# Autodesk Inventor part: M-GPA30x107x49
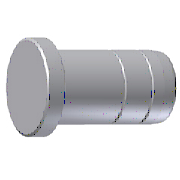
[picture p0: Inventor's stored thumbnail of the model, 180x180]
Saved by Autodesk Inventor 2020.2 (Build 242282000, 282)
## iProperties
Created: 2019-01
Part Number: M-GPA30x107x49
Material: SUJ 2
Description: KOŁEK PROWADZĄCY
Document SubType Name: Modeling
Designer: F.Stasiak
Standard Revision: 1
Manufacturer: FUTABA
Language: pl-PL
Size Designation: 30x107x49
Categories: <MemberInstance><Categories><Category DisplayName="Forma wtryskowa" InternalName="349578f2-f4d4-4954-8c09-8e99297a61c0" Mnemonic="MOLD"><Category DisplayName="K
Mass: 12.6115 g
Surface Area: 36.5267 cm^2
Volume: 12.6115 cm^3
Density: 7.85 g/cm^3
Appearance: Domyślna
Catalog Web Link: www.expertbooks.pl
Manager: www.cadconsulting.pl
Company: Fabian Stasiak CAD Consulting
IsCustomPart: 0
Author: F.Stasiak
Subject: Zbiór ćwiczeń. Autodesk Inventor 2020. Kurs Professional
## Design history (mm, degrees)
body "Solid1"
revolve "Obrót1" stored, may be unused: angle "d18" = 90 deg
feature "Zwój1" pitch "d37" = 19.33333 (= P); turns "d39" = 3; dims "d38" = 53.5 (derived), "d40" = 0, angle "d41" = 90 deg, angle "d42" = 90 deg, "d43" = 0, "d44" = 0
revolve "Obrót2" stored, may be unused: angle "d54" = 90 deg
revolve "Obrót3" stored, may be unused: angle "d55" = 90 deg
revolve "Obrót4" stored, may be unused: angle "d70" = 90 deg
fillet "Zaokrąglenie1" dims "d63" = 0.3
chamfer "Faza1" distance "d64" = 0.5; stored, may be unused: second distance "d65" = 2, angle "d66" = 45 deg
sketch "Sketch1"
  geometry: L1 (0, -114.465)-(0, 26.077) reference; L2 (0, 8)-(17.5, 8); L3 (17.5, 8)-(17.5, 0); L4 (17.5, 0)-(14.5, 0); L5 (14.5, 0)-(14.5, -1.5); L6 (14.5, -1.5)-(15, -1.5); L7 (15, -1.5)-(15, -41); L8 (15, -41)-(15, -41); L9 (15, -41)-(15, -93); L10 (15, -93)-(14.635, -97.174); L11 (12.642, -99)-(0, -99); L12 (0, 8)-(0, -99); A1 r 2 centre (12.642, -97) between (12.642, -99) and (14.635, -97.174); 2 further points
  constraints: 30 end point, 5 perpendicular, 4 parallel, 4 point on line, 2 point on circle, 2 tangent, 1 centre point, 1 collinear, 1 horizontal alignment
  dimensions: "d0" = 35 diameter of L3 L1 (= D); "d2" = 1.5 distance of L4.end L5.end; "d3" = 8 distance between parallel lines of L4 L2 (= H_); "d5" = 0.5 distance between parallel lines of L7 L5; "d6" = 49 distance between parallel lines of L2 L8 (= N_); "d7" = 30 diameter of L7 L1 (= d1); "d8" = 107 distance between parallel lines of L2 L11 (= L); "d9" = 30 diameter of L9 L1 (= d_); "d10" = 6 vertical distance of L9.end point (14.475, -99) (= E_); "d11" = 5 deg angle of L9 L10; "d12" = 2 radius of A1
sketch "Sketch2"
  geometry: L1 (15, -1.5)-(15, -93) reference; C1 r 0.5 at (15, -21.667)
  constraints: 1 centre point, 1 point on line
  dimensions: "d31" = 1 diameter of C1; "d68" = 71.33333 distance of L1.end C1.centre (derived)
sketch "Sketch3"
  geometry: L1 (0.5, 0)-(-0.5, 0); A1 r 0.5 centre (0, 0) between (-0.5, 0) and (0.5, 0) reference; A2 r 0.5 centre (0, 0) between (-0.5, 0) and (0.5, 0)
  constraints: 2 end point, 2 point on circle, 1 centre point, 1 coincident, 1 horizontal, 1 midpoint
  dimensions: "d71" = 0.5 radius of A2
sketch "Sketch4"
  geometry: L1 (-0.5, 0)-(0.5, 0); A1 r 0.5 centre (0, 0) between (-0.5, 0) and (0.5, 0) reference; A2 r 0.5 centre (0, 0) between (-0.5, 0) and (0.5, 0)
  constraints: 2 end point, 2 point on circle, 1 centre point, 1 coincident, 1 horizontal, 1 midpoint
  dimensions: "d72" = 0.5 radius of A2
sketch "Sketch5"
  geometry: L1 (15, -1.5)-(15, -93) reference; L2 (0, -106.8)-(0, 17.8) reference; C1 r 0.5 at (15, -30.583); C2 r 0.5 at (15, -66.25); 1 further point
  constraints: 2 centre point, 2 point on line, 1 equal radius
  dimensions: "d59" = 1 diameter of C1; "d61" = 35.66667 distance of C2.centre C1.centre (derived); "d69" = 26.75 distance of L1.end C2.centre (derived)
other parameters: "d_" = 30 [user parameter; used in 1 equation term], "L" = 107 [user parameter; used in 1 equation term], "d1" = 30 [user parameter; used in 1 equation term], "H_" = 8 [user parameter; used in 1 equation term], "D" = 35 [user parameter; used in 1 equation term], "N_" = 49 [user parameter; used in 1 equation term], "S_" = 38.66667 [user parameter], "P" = 19.33333 [user parameter; used in 1 equation term], "d56" = 0, "d58" = 0, "E_" = 6 [user parameter; used in 1 equation term], "d67" = 0
